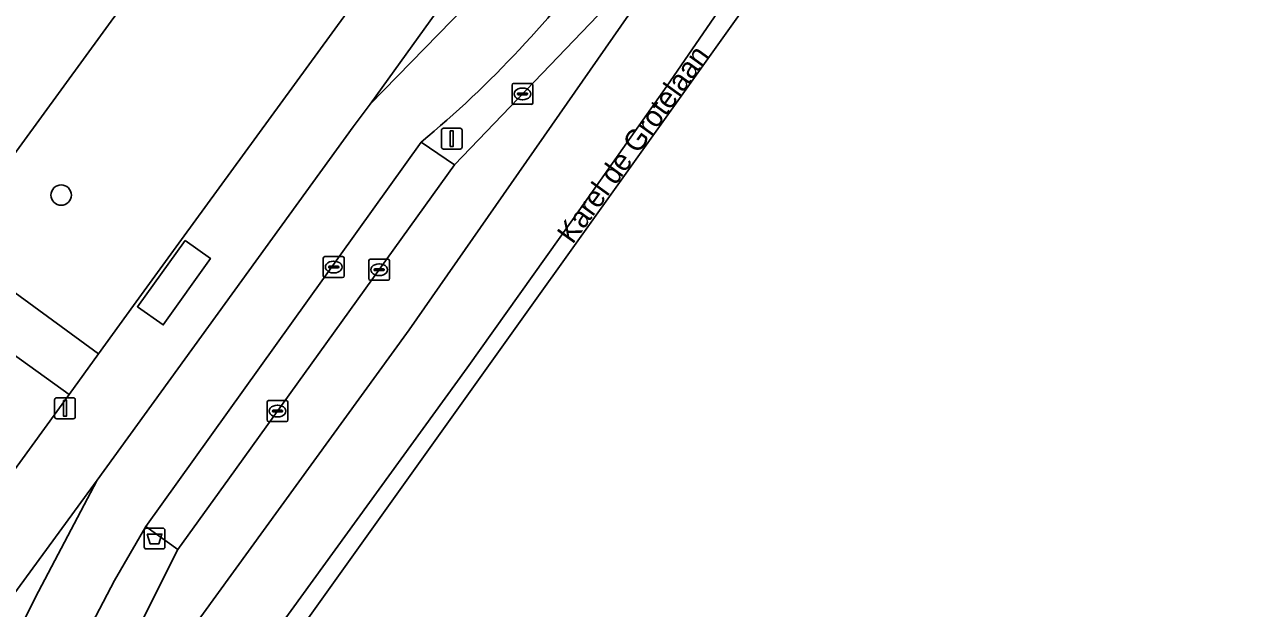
# Model space of a CAD drawing. Extents: x 159674 to 160531, y 382172 to 382904.
# Drawn here: x 160189.5 to 160248.5, y 382324.9 to 382352.9 of the extents above; entities that cross this region are included whole.
import ezdxf

# ---------------------------------------------------------------- set-up
doc = ezdxf.new("R2010")
doc.units = 0
for name, color, linetype in [('IMGEO_Afvalbak', 7, 'Continuous'), ('IMGEO_Berm_groen', 7, 'Continuous'), ('IMGEO_Boom', 7, 'Continuous'), ('IMGEO_Fietspad_gesloten', 7, 'Continuous'), ('IMGEO_Groenvoorziening', 7, 'Continuous'), ('IMGEO_Kolk', 7, 'Continuous'), ('IMGEO_Lichtmast', 7, 'Continuous'), ('IMGEO_Openbare_ruimte_label', 7, 'Continuous'), ('IMGEO_OVBaan_gesloten', 7, 'Continuous'), ('IMGEO_Rijbaan_lokaal_gesloten', 7, 'Continuous'), ('IMGEO_Rijbaan_lokaal_open', 7, 'Continuous'), ('IMGEO_Rioolput', 7, 'Continuous'), ('IMGEO_Voetpad_gesloten', 7, 'Continuous'), ('IMGEO_Voetpad_open', 7, 'Continuous')]:
    doc.layers.add(name, color=color, linetype=linetype)

msp = doc.modelspace()

# ---------------------------------------------------------------- linework, layer by layer
at = {"layer": 'IMGEO_Afvalbak'}
for p, q in [((160195.284, 382327.828), (160195.284, 382328.628)), ((160195.284, 382328.628), (160195.284, 382327.828)), ((160195.384, 382328.728), (160196.174, 382328.728)), ((160196.174, 382328.728), (160195.384, 382328.728)), ((160196.274, 382328.628), (160196.274, 382327.828)), ((160196.274, 382327.828), (160196.274, 382328.628)), ((160196.174, 382327.728), (160195.384, 382327.728)), ((160195.384, 382327.728), (160196.174, 382327.728))]:
    msp.add_line(p, q, dxfattribs=at)
msp.add_lwpolyline([(160195.427, 382328.442), (160196.131, 382328.442), (160195.982, 382327.972), (160195.576, 382327.972), (160195.427, 382328.442)], dxfattribs=at)
for centre, start, end in [((160195.384, 382328.628), 90, 180), ((160195.384, 382328.628), 90, 180), ((160196.174, 382328.628), 0, 90), ((160196.174, 382328.628), 360, 90), ((160195.384, 382327.828), 180, 270), ((160195.384, 382327.828), 180, 270), ((160196.174, 382327.828), 270, 0), ((160196.174, 382327.828), 270, 0)]:
    msp.add_arc(centre, 0.1, start, end, dxfattribs=at)
at = {"layer": 'IMGEO_Berm_groen'}
msp.add_lwpolyline([(160240.85, 382394.229), (160239.356, 382395.242), (160206.11, 382349.048), (160210.679, 382353.737), (160214.321, 382357.802), (160216.206, 382360.239)], close=True, dxfattribs=at)
for points in [[(160208.565, 382347.235), (160210.154, 382346.139), (160220.079, 382356.497), (160221.369, 382357.843), (160223.271, 382360.514)], [(160184.82, 382306.972), (160186.083, 382308.564), (160186.382, 382308.969), (160189.803, 382313.599), (160190.7, 382315.34), (160196.892, 382327.698), (160195.36, 382328.802), (160193.858, 382326.217), (160190.808, 382320.381), (160188.068, 382316.227), (160180.105, 382305.691), (160172.02, 382296.669), (160168.969, 382292.827), (160145.958, 382261.051)]]:
    msp.add_lwpolyline(points, dxfattribs=at)
msp.add_arc((160175.05, 382387.474), 52.368, 309.7908, 323.97071, dxfattribs=at)
at = {"layer": 'IMGEO_Boom'}
msp.add_circle((160191.301, 382344.693), 0.489, dxfattribs=at)
at = {"layer": 'IMGEO_Fietspad_gesloten'}
for points in [[(160217.401, 382356.671), (160222.364, 382363.518), (160224.126, 382365.95), (160243.252, 382392.338), (160243.322, 382392.439), (160245.561, 382395.649), (160246.525, 382397.047), (160244.544, 382399.324), (160240.85, 382394.229), (160216.206, 382360.239), (160214.321, 382357.802), (160210.679, 382353.737), (160206.11, 382349.048), (160205.291, 382347.967), (160193.022, 382331.032), (160190.048, 382325.389), (160188.543, 382322.341), (160176.949, 382306.659), (160170.726, 382299.839), (160168.85, 382297.646), (160168.66, 382297.704), (160140.992, 382259.471)], [(160145.958, 382261.051), (160168.969, 382292.827), (160172.02, 382296.669), (160180.105, 382305.691), (160188.068, 382316.227), (160190.808, 382320.381), (160193.858, 382326.217), (160195.36, 382328.802), (160208.565, 382347.235)]]:
    msp.add_lwpolyline(points, dxfattribs=at)
msp.add_arc((160175.05, 382387.474), 52.368, 309.7908, 323.97071, dxfattribs=at)
at = {"layer": 'IMGEO_Groenvoorziening'}
for points in [[(160178.065, 382426.137), (160223.044, 382393.348), (160187.51, 382344.568), (160186.917, 382344.985), (160186.028, 382343.745), (160185.319, 382342.757), (160193.09, 382337.087), (160194.774, 382339.399), (160197.076, 382342.559), (160239.715, 382401.084)], [(160138.96, 382376.616), (160131.133, 382365.857), (160178.05, 382331.678), (160177.395, 382330.658), (160184.698, 382325.533), (160191.681, 382335.131), (160184.594, 382340.228), (160178.492, 382331.846), (160164.216, 382342.237), (160149.986, 382352.594), (160135.756, 382362.951), (160141.858, 382371.334), (160144.138, 382369.674), (160146.342, 382372.701), (160140.649, 382376.845)]]:
    msp.add_lwpolyline(points, dxfattribs=at)
msp.add_lwpolyline([(160168.85, 382297.646), (160170.726, 382299.839), (160176.949, 382306.659), (160188.543, 382322.341), (160190.048, 382325.389), (160193.022, 382331.032), (160168.66, 382297.704)], close=True, dxfattribs=at)
at = {"layer": 'IMGEO_Kolk'}
for p, q in [((160212.917, 382349.119), (160212.917, 382349.971)), ((160212.992, 382350.045), (160213.844, 382350.045)), ((160213.176, 382349.539), (160213.176, 382349.551)), ((160213.614, 382349.502), (160213.216, 382349.502)), ((160213.219, 382349.588), (160213.617, 382349.588)), ((160213.405, 382349.825), (160213.43, 382349.825)), ((160213.66, 382349.551), (160213.66, 382349.539)), ((160213.918, 382349.971), (160213.918, 382349.119)), ((160213.844, 382349.045), (160212.992, 382349.045)), ((160213.428, 382349.265), (160213.403, 382349.265)), ((160206.042, 382340.689), (160206.042, 382341.541)), ((160206.117, 382341.615), (160206.969, 382341.615)), ((160206.53, 382341.395), (160206.555, 382341.395)), ((160207.043, 382341.541), (160207.043, 382340.689)), ((160206.301, 382341.109), (160206.301, 382341.121)), ((160206.739, 382341.072), (160206.341, 382341.072)), ((160206.344, 382341.158), (160206.742, 382341.158)), ((160206.553, 382340.835), (160206.528, 382340.835)), ((160206.785, 382341.121), (160206.785, 382341.109)), ((160206.969, 382340.615), (160206.117, 382340.615)), ((160201.172, 382333.913), (160201.172, 382334.765)), ((160201.247, 382334.839), (160202.099, 382334.839)), ((160202.173, 382334.765), (160202.173, 382333.913)), ((160201.431, 382334.333), (160201.431, 382334.345)), ((160201.869, 382334.296), (160201.471, 382334.296)), ((160201.474, 382334.382), (160201.872, 382334.382)), ((160201.66, 382334.619), (160201.685, 382334.619)), ((160201.915, 382334.345), (160201.915, 382334.333)), ((160202.099, 382333.839), (160201.247, 382333.839)), ((160201.683, 382334.059), (160201.658, 382334.059))]:
    msp.add_line(p, q, dxfattribs=at)
for points in [[(160212.917, 382349.119), (160212.917, 382349.971)], [(160212.992, 382350.045), (160213.844, 382350.045)], [(160213.918, 382349.971), (160213.918, 382349.119)], [(160213.844, 382349.045), (160212.992, 382349.045)], [(160206.042, 382340.689), (160206.042, 382341.541)], [(160206.117, 382341.615), (160206.969, 382341.615)], [(160207.043, 382341.541), (160207.043, 382340.689)], [(160206.969, 382340.615), (160206.117, 382340.615)], [(160201.172, 382333.913), (160201.172, 382334.765)], [(160201.247, 382334.839), (160202.099, 382334.839)], [(160202.173, 382334.765), (160202.173, 382333.913)], [(160202.099, 382333.839), (160201.247, 382333.839)]]:
    msp.add_lwpolyline(points, dxfattribs=at)
for centre, radius, start, end in [((160212.994, 382349.969), 0.0765, 91.55205, 178.44795), ((160212.994, 382349.969), 0.0765, 91.55205, 178.44795), ((160213.216, 382349.548), 0.0403, 85.87752, 175.75265), ((160213.213, 382349.538), 0.0366, 178.93798, 274.71019), ((160213.617, 382349.545), 0.043, 264.86636, 352.45326), ((160213.621, 382349.55), 0.0386, 1.73085, 96.63898), ((160213.842, 382349.969), 0.0765, 1.55205, 88.44795), ((160213.842, 382349.969), 0.0765, 1.55205, 88.44795), ((160212.994, 382349.121), 0.0765, 181.55205, 268.44795), ((160212.994, 382349.121), 0.0765, 181.55205, 268.44795), ((160213.842, 382349.121), 0.0765, 271.55205, 358.44795), ((160213.842, 382349.121), 0.0765, 271.55205, 358.44795), ((160206.119, 382341.539), 0.0765, 91.55205, 178.44795), ((160206.119, 382341.539), 0.0765, 91.55205, 178.44795), ((160206.967, 382341.539), 0.0765, 1.55205, 88.44795), ((160206.967, 382341.539), 0.0765, 1.55205, 88.44795), ((160206.119, 382340.691), 0.0765, 181.55205, 268.44795), ((160206.119, 382340.691), 0.0765, 181.55205, 268.44795), ((160206.341, 382341.118), 0.0403, 85.87752, 175.75265), ((160206.338, 382341.108), 0.0366, 178.93798, 274.71019), ((160206.742, 382341.115), 0.043, 264.86636, 352.45326), ((160206.746, 382341.12), 0.0386, 1.73085, 96.63898), ((160206.967, 382340.691), 0.0765, 271.55205, 358.44795), ((160206.967, 382340.691), 0.0765, 271.55205, 358.44795), ((160201.249, 382334.763), 0.0765, 91.55205, 178.44795), ((160201.249, 382334.763), 0.0765, 91.55205, 178.44795), ((160202.097, 382334.763), 0.0765, 1.55205, 88.44795), ((160202.097, 382334.763), 0.0765, 1.55205, 88.44795), ((160201.471, 382334.342), 0.0403, 85.87752, 175.75265), ((160201.468, 382334.332), 0.0366, 178.93798, 274.71019), ((160201.872, 382334.339), 0.043, 264.86636, 352.45326), ((160201.876, 382334.344), 0.0386, 1.73085, 96.63898), ((160201.249, 382333.915), 0.0765, 181.55205, 268.44795), ((160201.249, 382333.915), 0.0765, 181.55205, 268.44795), ((160202.097, 382333.915), 0.0765, 271.55205, 358.44795), ((160202.097, 382333.915), 0.0765, 271.55205, 358.44795)]:
    msp.add_arc(centre, radius, start, end, dxfattribs=at)
for centre, major_axis, ratio, start_param, end_param in [((160213.404, 382349.545), (-0.387, 0.002), 0.722429, 4.712389, 7.853982), ((160213.429, 382349.545), (-0.39, 0.002), 0.717154, 1.570796, 4.712389), ((160206.529, 382341.115), (-0.387, 0.002), 0.722429, 4.712389, 7.853982), ((160206.554, 382341.115), (-0.39, 0.002), 0.717154, 1.570796, 4.712389), ((160201.659, 382334.339), (-0.387, 0.002), 0.722429, 4.712389, 7.853982), ((160201.684, 382334.339), (-0.39, 0.002), 0.717154, 1.570796, 4.712389)]:
    msp.add_ellipse(centre, major_axis=major_axis, ratio=ratio, start_param=start_param, end_param=end_param, dxfattribs=at)
at = {"layer": 'IMGEO_Lichtmast'}
for p, q in [((160209.53, 382346.999), (160209.53, 382347.799)), ((160209.53, 382347.799), (160209.53, 382346.999)), ((160209.63, 382347.899), (160210.42, 382347.899)), ((160210.42, 382347.899), (160209.63, 382347.899)), ((160210.52, 382347.799), (160210.52, 382346.999)), ((160210.52, 382346.999), (160210.52, 382347.799)), ((160210.42, 382346.899), (160209.63, 382346.899)), ((160209.63, 382346.899), (160210.42, 382346.899)), ((160190.989, 382334.076), (160190.989, 382334.876)), ((160190.989, 382334.876), (160190.989, 382334.076)), ((160191.089, 382334.976), (160191.879, 382334.976)), ((160191.879, 382334.976), (160191.089, 382334.976)), ((160191.979, 382334.876), (160191.979, 382334.076)), ((160191.979, 382334.076), (160191.979, 382334.876)), ((160191.879, 382333.976), (160191.089, 382333.976)), ((160191.089, 382333.976), (160191.879, 382333.976))]:
    msp.add_line(p, q, dxfattribs=at)
for points in [[(160209.95, 382347.774), (160210.1, 382347.774), (160210.1, 382347.024), (160209.95, 382347.024), (160209.95, 382347.774)], [(160191.409, 382334.851), (160191.559, 382334.851), (160191.559, 382334.101), (160191.409, 382334.101), (160191.409, 382334.851)]]:
    msp.add_lwpolyline(points, dxfattribs=at)
for centre, start, end in [((160209.63, 382347.799), 90, 180), ((160209.63, 382347.799), 90, 180), ((160210.42, 382347.799), 0, 90), ((160210.42, 382347.799), 360, 90), ((160209.63, 382346.999), 180, 270), ((160209.63, 382346.999), 180, 270), ((160210.42, 382346.999), 270, 0), ((160210.42, 382346.999), 270, 0), ((160191.089, 382334.876), 90, 180), ((160191.089, 382334.876), 90, 180), ((160191.879, 382334.876), 0, 90), ((160191.879, 382334.876), 360, 90), ((160191.089, 382334.076), 180, 270), ((160191.089, 382334.076), 180, 270), ((160191.879, 382334.076), 270, 0), ((160191.879, 382334.076), 270, 0)]:
    msp.add_arc(centre, 0.1, start, end, dxfattribs=at)
at = {"layer": 'IMGEO_OVBaan_gesloten'}
msp.add_lwpolyline([(160207.981, 382338.24), (160220.449, 382356.135), (160220.079, 382356.497), (160210.154, 382346.139), (160199.371, 382331.135), (160196.892, 382327.698), (160190.7, 382315.34), (160191.144, 382315.025)], close=True, dxfattribs=at)
at = {"layer": 'IMGEO_Rijbaan_lokaal_gesloten'}
for points in [[(160192.838, 382311.695), (160210.756, 382336.417), (160215.818, 382343.508), (160220.337, 382349.919), (160231.455, 382366.109), (160242.351, 382382.458), (160246.916, 382389.2), (160244.06, 382391.306), (160233.945, 382376.185), (160231.607, 382372.698), (160229.041, 382368.91), (160227.315, 382366.396), (160225.613, 382363.919), (160223.271, 382360.514), (160221.369, 382357.843), (160220.079, 382356.497), (160220.449, 382356.135), (160207.981, 382338.24), (160191.144, 382315.025)], [(160145.171, 382242.117), (160150.117, 382250.187), (160180.965, 382293.377), (160248.546, 382387.998), (160246.916, 382389.2), (160242.351, 382382.458), (160231.455, 382366.109), (160220.337, 382349.919), (160215.818, 382343.508), (160210.756, 382336.417), (160192.838, 382311.695), (160176.654, 382289.391), (160157.705, 382263.245), (160150.736, 382253.782), (160146.323, 382248.473), (160143.704, 382245.649), (160140.929, 382242.92), (160138.052, 382240.3), (160135.114, 382237.83), (160132.08, 382235.516), (160128.892, 382233.237), (160124.916, 382230.602), (160123.889, 382229.984), (160126.874, 382227.764)]]:
    msp.add_lwpolyline(points, dxfattribs=at)
at = {"layer": 'IMGEO_Rijbaan_lokaal_open'}
msp.add_lwpolyline([(160142.527, 382377.215), (160173.093, 382355.026), (160186.917, 382344.985), (160187.51, 382344.568), (160223.044, 382393.348), (160178.065, 382426.137)], dxfattribs=at)
msp.add_lwpolyline([(160196.892, 382327.698), (160199.371, 382331.135), (160210.154, 382346.139), (160208.565, 382347.235), (160195.36, 382328.802)], close=True, dxfattribs=at)
at = {"layer": 'IMGEO_Rioolput'}
for p, q in [((160203.866, 382340.818), (160203.866, 382341.67)), ((160203.941, 382341.744), (160204.793, 382341.744)), ((160204.125, 382341.238), (160204.125, 382341.25)), ((160204.168, 382341.287), (160204.566, 382341.287)), ((160204.354, 382341.524), (160204.379, 382341.524)), ((160204.609, 382341.25), (160204.609, 382341.238)), ((160204.867, 382341.67), (160204.867, 382340.818)), ((160204.793, 382340.744), (160203.941, 382340.744)), ((160204.563, 382341.201), (160204.165, 382341.201)), ((160204.377, 382340.964), (160204.352, 382340.964))]:
    msp.add_line(p, q, dxfattribs=at)
for points in [[(160203.866, 382340.818), (160203.866, 382341.67)], [(160203.941, 382341.744), (160204.793, 382341.744)], [(160204.867, 382341.67), (160204.867, 382340.818)], [(160204.793, 382340.744), (160203.941, 382340.744)]]:
    msp.add_lwpolyline(points, dxfattribs=at)
for centre, radius, start, end in [((160203.943, 382341.668), 0.0765, 91.55205, 178.44795), ((160203.943, 382341.668), 0.0765, 91.55205, 178.44795), ((160204.165, 382341.247), 0.0403, 85.87752, 175.75265), ((160204.162, 382341.237), 0.0366, 178.93798, 274.71019), ((160204.566, 382341.244), 0.043, 264.86636, 352.45326), ((160204.57, 382341.249), 0.0386, 1.73085, 96.63898), ((160204.791, 382341.668), 0.0765, 1.55205, 88.44795), ((160204.791, 382341.668), 0.0765, 1.55205, 88.44795), ((160203.943, 382340.82), 0.0765, 181.55205, 268.44795), ((160203.943, 382340.82), 0.0765, 181.55205, 268.44795), ((160204.791, 382340.82), 0.0765, 271.55205, 358.44795), ((160204.791, 382340.82), 0.0765, 271.55205, 358.44795)]:
    msp.add_arc(centre, radius, start, end, dxfattribs=at)
for centre, major_axis, ratio, start_param, end_param in [((160204.353, 382341.244), (-0.387, 0.002), 0.722429, 4.712389, 7.853982), ((160204.378, 382341.244), (-0.39, 0.002), 0.717154, 1.570796, 4.712389)]:
    msp.add_ellipse(centre, major_axis=major_axis, ratio=ratio, start_param=start_param, end_param=end_param, dxfattribs=at)
at = {"layer": 'IMGEO_Voetpad_gesloten'}
msp.add_lwpolyline([(160197.244, 382342.511), (160194.961, 382339.345), (160196.194, 382338.471), (160198.455, 382341.656)], close=True, dxfattribs=at)
at = {"layer": 'IMGEO_Voetpad_open'}
for points in [[(160239.715, 382401.084), (160197.076, 382342.559), (160194.774, 382339.399), (160193.09, 382337.087), (160191.681, 382335.131), (160184.698, 382325.533), (160177.299, 382315.365), (160176.307, 382314.001), (160163.578, 382296.507), (160155.71, 382285.693), (160154.089, 382283.466), (160146.738, 382273.362), (160137.034, 382260.024), (160136.508, 382258.728)], [(160193.022, 382331.032), (160205.291, 382347.967), (160206.11, 382349.048), (160239.356, 382395.242), (160240.85, 382394.229), (160244.544, 382399.324)], [(160140.992, 382259.471), (160168.66, 382297.704), (160193.022, 382331.032)]]:
    msp.add_lwpolyline(points, dxfattribs=at)
for points in [[(160193.09, 382337.087), (160185.319, 382342.757), (160186.028, 382343.745), (160181.164, 382347.356), (160179.04, 382344.271), (160184.594, 382340.228), (160191.681, 382335.131)], [(160197.244, 382342.511), (160198.455, 382341.656), (160196.194, 382338.471), (160194.961, 382339.345)]]:
    msp.add_lwpolyline(points, close=True, dxfattribs=at)

# ---------------------------------------------------------------- texts
at = {"layer": 'IMGEO_Openbare_ruimte_label'}
msp.add_text('Karel de Grotelaan', height=1, rotation=54.03584, dxfattribs=at).set_placement((160215.816, 382342.301))

doc.saveas('drawing.dxf')
